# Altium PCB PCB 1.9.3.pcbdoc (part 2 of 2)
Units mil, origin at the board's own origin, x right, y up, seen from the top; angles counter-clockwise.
Board outline 4192.9 x 2374.1 mil, 2 copper layers (Top Layer, Bottom Layer), stack 62.2 mil thick; 67 components, 68 nets, 279 pads, 489 vias.
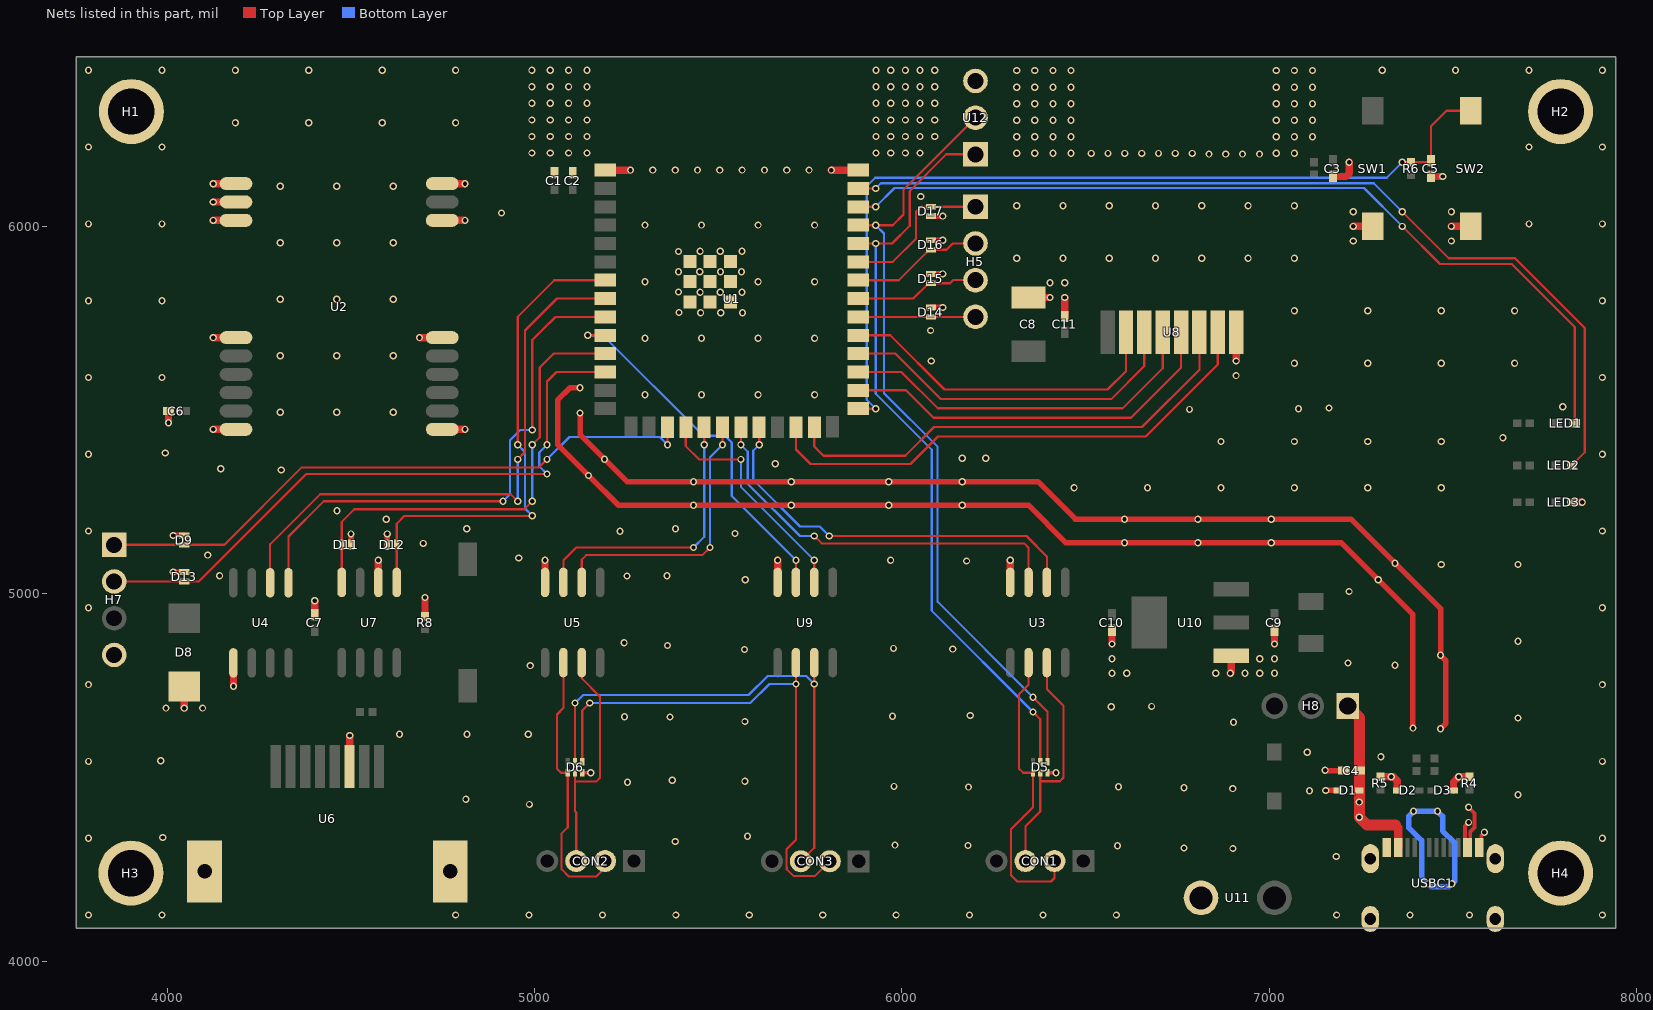
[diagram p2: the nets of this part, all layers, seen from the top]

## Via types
v1: diameter 19.7, hole 11.8, Top Layer to Bottom Layer, 489 vias

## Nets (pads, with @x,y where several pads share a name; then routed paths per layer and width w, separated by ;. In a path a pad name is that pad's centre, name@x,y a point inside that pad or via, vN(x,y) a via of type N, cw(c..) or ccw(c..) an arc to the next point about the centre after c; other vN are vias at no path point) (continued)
GND: C1.1 C2.1 C3.1 C4.1 C5.1 C6.1 C7.1 C8.2 C9.2 C10.1 C11.2 D1.1 D2.1 D3.1 D5.3 D6.3 D8.2 D9.1 D11.2 D12.2 D13.1 D14.1 D15.1 D16.1 D17.1 H1.1 H2.1 H3.1 H4.1 H7.4 LED3.1 R4.1 R5.1 R8.1 SW1.1 SW2.1 U1.1 U1.40 U1.41 U2.1 U2.2 U2.3 U2.4 U2.9 U2.10 U2.15 U2.16 U2.18 U3.4 U4.5 U5.4 U6.6 U6.9 U6.10 U7.2 U8.8 U9.4 U10.1 U11.1 U12.3 USBC1.0 USBC1.1 USBC1.2 USBC1.3 USBC1.A1 USBC1.A12 USBC1.B1 USBC1.B12 | length 8944.7
  Top Layer w6: v1(7152.7,4519.7) v1@7153.8,4518.7
  Top Layer w10: D6.3@5129.1,4512.9 v1(5152.1,4512.9) ; D5.3@6396.4,4512.9 v1(6419.4,4512.9) ; USBC1.A12@7578.1,4309.2 7578.1,4342.1 v1(7586.7,4350.7)
  Top Layer w15: v1(4015.1,5059.4) D13.1@4044.9,5059.4 ; v1(4015.1,5159.4) D9.1@4044.9,5159.4 ; D11.2@4499.3,5133.8 v1(4499.3,5163.6) ; D12.2@4598.1,5133.8 v1(4598.1,5163.6) ; v1(5123.1,5492.7) 5123.1,5433.7 v1(5189.7,5367.1) 5251.1,5305.7 v1(5432.1,5305.7) v1(5698.1,5305.7) v1(5964.1,5305.7) v1(6164.1,5305.7) 6370.6,5305.7 6472.6,5203.7 v1(6606.1,5203.7) v1(6806.1,5203.7) v1(7006.1,5203.7) 7223.1,5203.7 v1(7343.1,5083.7) 7467.1,4959.7 v1(7467.1,4832.7) 7481.9,4818 7481.9,4647.5 v1(7467.1,4632.7) ; v1(5123.1,5561.7) 5096.1,5561.7 5062.1,5527.7 5062.1,5406.7 v1(5146,5322.8) 5227.1,5241.7 v1(5432.1,5241.7) v1(5698.1,5241.7) v1(5964.1,5241.7) v1(6164.1,5241.7) 6344.1,5241.7 6446.1,5139.7 v1(6606.1,5139.7) v1(6806.1,5139.7) v1(7006.1,5139.7) 7196.6,5139.7 v1(7297.8,5038.5) 7392.1,4944.2 v1@7392.1,4632.7 ; D14.1@6079.1,5780.4 v1(6111.1,5780.4) ; D15.1@6079.1,5871.9 v1(6111.1,5871.9) ; D16.1@6079.1,5963.4 v1(6111.1,5963.4) ; D17.1@6079.1,6029.2 v1(6111.1,6029.2) ; v1@7153.8,4518.7 C4.1@7203,4518.7 ; v1(7154.7,4464.7) D1.1@7186.9,4464.7
  Top Layer w20: v1(4001.9,5466.3) C6.1@4001.9,5498.3 ; v1(4044.9,4689) D8.2@4044.9,4747.9 ; v1(4123.7,5448.3) U2.9@4185.9,5448.3 ; v1(4123.7,5698.3) U2.4@4185.9,5698.3 ; v1(4123.7,6017.6) U2.3@4185.9,6017.6 ; v1(4123.7,6067.6) U2.2@4185.9,6067.6 ; v1(4123.7,6117.6) U2.1@4185.9,6117.6 ; v1(4178.8,4748.7) U4.5@4178.8,4812.1 ; C7.1@4400.1,4943.6 v1(4400.1,4981.7) ; U6.6@4495.7,4529.7 v1(4495.7,4614.2) ; U7.2@4573.7,5031.3 v1(4573.7,5091.7) ; v1(4685.5,5698.3) U2.15@4747.7,5698.3 ; R8.1@4700.8,4939.2 v1(4700.8,4990.1) ; U2.10@4747.7,5448.3 v1(4809.8,5448.3) ; U2.16@4747.7,6017.6 v1(4809.8,6017.6) ; U2.18@4747.7,6117.6 v1(4809.8,6117.6) ; U5.4@5027.6,5031.3 v1(5027.6,5091.7) ; U1.1@5191.7,6154.6 v1(5260.6,6154.6) ; U9.4@5661.2,5031.3 v1(5661.2,5091.7) ; v1(5807.8,6154.6) U1.40@5880.7,6154.6 ; U3.4@6294.8,5031.3 v1(6294.8,5091.7) ; C8.2@6344.7,5807.5 v1(6403.3,5807.5) ; C11.2@6443.3,5755.7 v1(6443.3,5807.5) ; v1(6572.1,4863.7) C10.1@6572.1,4900.7 ; v1(6894.7,4783.7) 6897.2,4786.2 U10.1@6897.2,4831.6 ; v1(6910.3,5634.7) U8.8@6910.3,5712.8 ; v1(7014.7,4863.7) C9.2@7014.7,4900.7 ; C3.1@7174.1,6137.3 7209.7,6137.3 7218.1,6145.7 v1(7218.1,6175.8) ; v1(7229.7,6001.3) SW1.1@7282.1,6001.3 ; R5.1@7303.2,4501.8 7338.7,4501.8 7349.6,4490.8 D2.1@7349.6,4464.7 ; C5.1@7441.1,6137.3 v1(7473.1,6137.3) ; v1(7496.7,6001.3) SW2.1@7549.1,6001.3 ; D3.1@7502.7,4464.7 7502.7,4487.8 v1(7516.7,4501.8) R4.1@7546.2,4501.8 ; LED3.1@7824.4,5249.9 v1(7852.9,5249.9)
  Bottom Layer w15: 7380.7,4362.7 7380.7,4394.7 v1(7393.7,4407.7) v1(7458.7,4407.7) 7472.7,4393.7 7472.7,4354.7 7506,4321.5 7506,4218.6 v1(7498.1,4210.7) 7489.1,4201.8 7442.1,4201.8 v1(7433.1,4210.7) 7415.7,4228.1 7415.7,4327.7 7380.7,4362.7
  other v1: 3784.1,4125.5 3984.1,4125.5 4784.1,4125.5 4984.1,4125.5 5184.1,4125.5 5384.1,4125.5 5584.1,4125.5 5784.1,4125.5 5984.1,4125.5 6184.1,4125.5 6384.1,4125.5 6584.1,4125.5 7184.1,4125.5 7384.1,4125.5 7546.1,4125.5 7908.1,4125.5 7183.1,4284.7 6901.5,4306.7 6768.1,4307.7 6587.1,4313.7 6180.1,4314.7 5981.1,4315.7 5382.1,4325.7 3784.1,4334.7 7908.1,4334.7 3986.1,4336.7 5579.1,4339.7 4985.1,4426.7 4812.1,4440.7 7678.1,4452.7 7110.1,4463.7 6901.1,4469.7 6768.1,4471.7 6181.1,4473.7 6590.1,4474.7 5978.1,4475.7 5252.1,4486.7 5572.1,4489.7 5374.1,4492.7 7332.7,4501.8 3784.1,4543.8 7908.1,4543.8 3981.1,4545.7 7304.7,4556.7 7104.1,4568.7 4631.1,4617.7 4815.1,4617.7 4982.1,4617.7 7392.1,4634.5 6903.1,4650.7 5572.1,4652.7 7678.1,4661.9 5368.1,4664.7 5244.1,4665.7 5974.1,4666.7 6186.1,4668.7 3994.9,4689 4094.9,4689 6570.1,4692.7 6680.1,4693.7 3784.1,4753 7908.1,4753 6572.1,4783.7 6612.1,4783.7 6854.7,4783.7 6934.7,4783.7 6974.7,4783.7 7014.7,4783.7 4987.1,4804.7 7343.1,4805.7 7215.1,4811.7 6572.1,4823.7 6974.7,4823.7 7014.7,4823.7 5571.1,4848.7 6138.1,4849.7 5977.1,4851.7 5361.1,4859.7 5243.1,4866.7 7678.1,4871.1 3784.1,4962.2 7908.1,4962.2 7218.1,5006.7 5573.1,5038.7 5251.1,5048.7 4141.1,5049.7 5360.1,5049.7 7469,5080.3 7678.1,5080.3 6176.1,5089.7 5969.1,5091.7 4956.1,5097.7 4109.1,5105.7 4696.1,5137.7 5545.1,5164.7 3784.1,5171.4 5232.1,5170.7 7908.1,5171.4 4814.1,5177.7 5383.1,5177.7 4595.1,5203.7 4461.1,5226.7 6469,5289.4 6669,5289.4 6869,5289.4 7069,5289.4 7269,5289.4 7469,5289.4 4309.1,5337.7 4144.1,5340.7 5655.1,5354.7 6164.1,5369.7 6228.1,5369.7 3784.1,5380.6 7908.1,5380.6 3993.1,5383.7 6869,5415.4 7069,5415.4 7269,5415.4 7469,5415.4 7637.1,5425.7 4306.1,5494.7 4460.1,5494.7 4614.1,5494.7 6783.1,5502.7 7080.1,5504.7 7163.1,5506.7 7800.1,5509.7 5300.1,5542.7 5454.1,5542.7 5608.1,5542.7 5762.1,5542.7 3784.1,5589.7 3984.1,5589.7 7908.1,5589.7 6910.3,5594.7 7069,5628.4 7269,5628.4 7469,5628.4 7669,5628.4 6080.1,5634.7 4306.1,5648.7 4460.1,5648.7 4614.1,5648.7 5300.1,5696.7 5454.1,5696.7 5608.1,5696.7 5762.1,5696.7 6078.1,5717.7 5451.5,5765.7 5506.5,5765.7 5565.5,5765.7 5392.5,5766.7 7069,5771.4 7269,5771.4 7469,5771.4 7669,5771.4 3784.1,5798.9 3984.1,5798.9 7908.1,5798.9 4306.1,5802.7 4460.1,5802.7 4614.1,5802.7 5450.1,5821.7 5505.1,5821.7 5564.1,5821.7 5391.1,5822.7 6403.3,5847.5 6443.3,5847.5 5300.1,5850.7 5608.1,5850.7 5762.1,5850.7 5391.1,5877.7 5449.1,5877.7 5505.8,5877.7 5562.7,5877.7 6312.6,5914.4 6438.6,5914.4 6564.7,5914.4 6690.8,5914.4 6816.8,5914.4 6942.9,5914.4 7069,5914.4 5391.1,5932.7 5450.1,5933.7 5505.1,5933.7 5564.1,5933.7 4306.1,5956.7 4460.1,5956.7 4614.1,5956.7 7229.7,5961.3 7496.7,5961.3 5300.1,6004.7 5454.1,6004.7 5608.1,6004.7 5762.1,6004.7 3784.1,6008.1 3984.1,6008.1 7708.1,6008.1 7908.1,6008.1 4909.1,6037.7 7229.7,6041.3 7496.7,6041.3 6312.6,6057.4 6438.6,6057.4 6564.7,6057.4 6690.8,6057.4 6816.8,6057.4 6942.9,6057.4 7069,6057.4 6051.1,6082.7 4306.1,6110.7 4460.1,6110.7 4614.1,6110.7 5321.4,6154.6 5382.2,6154.6 5443,6154.6 5503.8,6154.6 5564.6,6154.6 5625.4,6154.6 5686.2,6154.6 5747,6154.6 6836.3,6198.1 6882.1,6198.1 6927.9,6198.1 6973.8,6198.1 6312.6,6200.4 6361.9,6200.4 6411.3,6200.4 6460.6,6200.4 6515.5,6200.1 6561.3,6200.1 6607.1,6200.1 6653,6200.1 6698.8,6200.1 6744.6,6200.1 6790.5,6200.1 7019.6,6200.4 7069,6200.4 4991.9,6201.3 5041.9,6201.3 5091.9,6201.3 5141.9,6201.3 5929.3,6201.3 5969.3,6201.3 6009.3,6201.3 6049.3,6201.3 3784.1,6217.3 3984.1,6217.3 7708.1,6217.3 7908.1,6217.3 4991.9,6246.3 5041.9,6246.3 5091.9,6246.3 5141.9,6246.3 5929.3,6246.3 5969.3,6246.3 6009.3,6246.3 6049.3,6246.3 6089.3,6246.3 6312.6,6245.5 6361.9,6245.5 6411.3,6245.5 6460.6,6245.5 7019.6,6245.5 7069,6245.5 7118.3,6245.5 4184.1,6283.5 4384.1,6283.5 4584.1,6283.5 4784.1,6283.5 6312.6,6290.5 6361.9,6290.5 6411.3,6290.5 6460.6,6290.5 7019.6,6290.5 7069,6290.5 7118.3,6290.5 4991.9,6291.3 5041.9,6291.3 5091.9,6291.3 5141.9,6291.3 5929.3,6291.3 5969.3,6291.3 6009.3,6291.3 6049.3,6291.3 6089.3,6291.3 4991.9,6336.4 5041.9,6336.4 5091.9,6336.4 5141.9,6336.4 5929.3,6336.4 5969.3,6336.4 6009.3,6336.4 6049.3,6336.4 6089.3,6336.4 6312.6,6335.6 6361.9,6335.6 6411.3,6335.6 6460.6,6335.6 7019.6,6335.6 7069,6335.6 7118.3,6335.6 4991.9,6381.4 5041.9,6381.4 5091.9,6381.4 5141.9,6381.4 5929.3,6381.4 5969.3,6381.4 6009.3,6381.4 6049.3,6381.4 6089.3,6381.4 6312.6,6380.6 6361.9,6380.6 6411.3,6380.6 6460.6,6380.6 7019.6,6380.6 7069,6380.6 7118.3,6380.6 3784.1,6426.5 3984.1,6426.5 4184.1,6426.5 4384.1,6426.5 4584.1,6426.5 4784.1,6426.5 4991.9,6426.5 5041.9,6426.5 5091.9,6426.5 5141.9,6426.5 5929.3,6426.5 5969.3,6426.5 6009.3,6426.5 6049.3,6426.5 6089.3,6426.5 6312.6,6425.7 6361.9,6425.7 6411.3,6425.7 6460.6,6425.7 7019.6,6425.7 7069,6425.7 7118.3,6425.7 7308.1,6426.5 7508.1,6426.5 7708.1,6426.5 7908.1,6426.5
IO0: C5.2 R6.1 SW2.2 U1.27 | length 2448.8
  Top Layer w6: U1.27@5880.7,5504.6 v1(5928.4,5504.6) ; v1(7363.1,6175.8) R6.1@7387.1,6175.8 7436.7,6175.8 C5.2@7441.1,6180.3 7441.1,6273.7 7483.6,6316.3 SW2.2@7549.1,6316.3
  Bottom Layer w6: v1(5928.4,5504.6) 5904.1,5529 5904.1,6110.7 5927.1,6133.7 7321,6133.7 v1(7363.1,6175.8)
IO39: D14.2 H5.4 U1.32 | length 319.7
  Top Layer w6: U1.32@5880.7,5754.6 6200.1,5754.6 H5.4@6200.3,5754.8
IO40: D15.2 H5.3 U1.33 | length 340.4
  Top Layer w6: U1.33@5880.7,5804.6 6031,5804.6 6072.6,5846.3 D15.2@6079.1,5846.3 6130.6,5846.3 6139.2,5854.8 H5.3@6200.3,5854.8
IO41: D16.2 H5.2 U1.34 | length 361.1
  Top Layer w6: U1.34@5880.7,5854.6 5991,5854.6 6074.1,5937.8 D16.2@6079.1,5937.8 6121.5,5937.8 6138.6,5954.8 H5.2@6200.3,5954.8
IO42: D17.2 H5.1 U1.35 | length 424.6
  Top Layer w6: U1.35@5880.7,5904.6 5975,5904.6 6038.1,5967.7 6038.1,6040.7 6052.2,6054.8 D17.2@6079.1,6054.8 H5.1@6200.3,6054.8
LED1_INVERTER: LED2.1 U1.39 | length 2538
  Top Layer w6: U1.39@5880.7,6104.6 v1(5928.4,6104.6) ; v1(7363.1,6041.3) 7489.6,5914.7 7670.1,5914.7 7860.1,5724.7 7860.1,5385.6 LED2.1@7824.4,5349.9
  Bottom Layer w6: v1(5928.4,6104.6) 5942.5,6118.7 7285.6,6118.7 v1(7363.1,6041.3)
LED1_NETWORK: LED1.2 U1.38 | length 2392.2
  Top Layer w6: U1.38@5880.7,6054.6 v1(5928.4,6054.6) ; v1(7363.1,6001.3) 7465.6,5898.7 7661.1,5898.7 7832.7,5727.1 LED1.2@7832.7,5464.9
  Bottom Layer w6: v1(5928.4,6054.6) 5979.5,6105.7 7258.6,6105.7 v1(7363.1,6001.3)
MPPT1_RX: U1.20 U5.2 | length 767.1
  Top Layer w6: U5.2@5127.6,5031.3 5127.6,5093.2 5140.1,5105.7 5456.2,5105.7 v1(5477.2,5126.7) ; v1(5511.2,5406.5) U1.20@5511.2,5454.3
  Bottom Layer w6: v1(5477.2,5126.7) 5477.2,5372.5 v1(5511.2,5406.5)
MPPT1_TX: U1.19 U5.3 | length 768.7
  Top Layer w6: U5.3@5077.6,5031.3 5077.6,5091.2 5113.1,5126.7 v1(5432.1,5126.7) ; v1(5461.2,5406.5) U1.19@5461.2,5454.3
  Bottom Layer w6: v1(5432.1,5126.7) 5461.2,5155.9 v1(5461.2,5406.5)
MPPT2_RX: U1.18 U9.2 | length 634.7
  Top Layer w6: U1.18@5411.2,5454.3 5411.2,5402.6 5447.3,5366.5 v1(5561.2,5366.5) ; U9.2@5761.2,5031.3 v1(5761.2,5091.7)
  Bottom Layer w6: v1(5561.2,5366.5) 5561.2,5291.7 v1(5761.2,5091.7)
MPPT2_TX: U1.10 U9.3 | length 1014.6
  Top Layer w6: v1(5144,5704.6) U1.10@5191.7,5704.6 ; U9.3@5711.2,5031.3 v1(5711.2,5091.7)
  Bottom Layer w6: v1(5144,5704.6) 5185.2,5704.6 5459.1,5430.7 5518.1,5430.7 5536.1,5412.7 5536.1,5266.8 v1(5711.2,5091.7)
NRF_CE: U1.31 U8.2 | length 917.6
  Top Layer w6: U1.31@5880.7,5704.6 5968.2,5704.6 6116.1,5556.7 6560.1,5556.7 6610.3,5606.9 U8.2@6610.3,5712.8
NRF_CS: U1.30 U8.3 | length 960.2
  Top Layer w6: U1.30@5880.7,5654.6 5982.2,5654.6 6106.1,5530.7 6570.1,5530.7 6660.3,5620.9 U8.3@6660.3,5712.8
NRF_IRQ: U1.24 U8.7 | length 1426.6
  Top Layer w6: U1.24@5711.2,5454.3 5711.2,5393.6 5751.1,5353.7 6023.1,5353.7 6098.1,5428.7 6664.1,5428.7 6860.3,5624.9 U8.7@6860.3,5712.8
NRF_MISO: U1.25 U8.6 | length 1311
  Top Layer w6: U1.25@5761.2,5454.3 5761.2,5401.6 5786.1,5376.7 6009.1,5376.7 6087.1,5454.7 6654.1,5454.7 6810.3,5610.9 U8.6@6810.3,5712.8
NRF_MOSI: U1.28 U8.5 | length 1063.9
  Top Layer w6: U1.28@5880.7,5554.6 6011.2,5554.6 6086.1,5479.7 6624.1,5479.7 6760.3,5615.9 U8.5@6760.3,5712.8
NRF_SCK: U1.29 U8.4 | length 1013.7
  Top Layer w6: U1.29@5880.7,5604.6 5998.2,5604.6 6097.1,5505.7 6601.1,5505.7 6710.3,5614.9 U8.4@6710.3,5712.8
OLED_SCL: D13.2 H7.2 U1.12 | length 1739.4
  Top Layer w6: H7.2@3853.9,5033.8 D13.2@4044.9,5033.8 4084.2,5033.8 4376.9,5326.5 v1(5033.1,5326.5) ; v1(5033.1,5406.5) 5033.1,5578.7 5059,5604.6 U1.12@5191.7,5604.6
  Bottom Layer w6: v1(5033.1,5326.5) 5012.1,5347.5 5012.1,5385.5 v1(5033.1,5406.5)
OLED_SDA: D9.2 H7.1 U1.17 | length 1685.6
  Top Layer w6: H7.1@3853.9,5133.8 D9.2@4044.9,5133.8 4154.2,5133.8 4365.1,5344.7 5011.3,5344.7 v1(5033.1,5366.5) ; v1(5361.2,5406.5) U1.17@5361.2,5454.3
  Bottom Layer w6: v1(5033.1,5366.5) 5094.3,5427.7 5340,5427.7 v1(5361.2,5406.5)
PY_CAN_RX: D11.1 U1.11 U7.4 | length 1274.3
  Top Layer w6: U7.4@4473.7,5031.3 D11.1@4473.7,5133.8 4473.7,5196.3 4508.1,5230.7 4971.1,5230.7 v1(4993.1,5252.7) ; v1(4993.1,5406.5) 5013.1,5426.5 5013.1,5616.7 5051,5654.6 U1.11@5191.7,5654.6
  Bottom Layer w6: v1(4993.1,5252.7) v1(4993.1,5406.5)
PY_CAN_TX: D12.1 U1.7 U7.1 | length 1376.8
  Top Layer w6: U7.1@4623.7,5031.3 D12.1@4623.7,5133.8 4623.7,5191.3 4645.1,5212.7 v1(4993.1,5212.7) ; v1(4953.1,5406.5) 4953.1,5754.7 5053,5854.6 U1.7@5191.7,5854.6
  Bottom Layer w6: v1(4953.1,5406.5) 4973.1,5386.5 4973.1,5232.7 v1(4993.1,5212.7)
RE#: U1.8 U4.2 | length 1571.5
  Top Layer w6: U4.2@4278.8,5030.4 4278.8,5135.4 4415.1,5271.7 4934.1,5271.7 v1(4953.1,5252.7) ; v1(4953.1,5366.5) 4973.1,5386.5 4973.1,5717.7 5060,5804.6 U1.8@5191.7,5804.6
  Bottom Layer w6: v1(4953.1,5252.7) v1(4953.1,5366.5)
RO: U1.9 U4.1 | length 1466.4
  Top Layer w6: U4.1@4328.8,5030.4 4328.8,5156.4 4425.1,5252.7 v1(4913.1,5252.7) ; v1(4993.1,5446.5) 4993.1,5691.7 5019.6,5718.2 5056,5754.6 U1.9@5191.7,5754.6
  Bottom Layer w6: v1(4913.1,5252.7) 4932.1,5271.7 4932.1,5418.7 4959.9,5446.5 v1(4993.1,5446.5)
RX1: CON1.3 D5.2 U3.7 | length 656.9
  Top Layer w6: CON1.3@6336.6,4272.2 6336.6,4367.3 6376.7,4407.4 6376.7,4489.7 ; D5.2@6376.7,4512.9 6376.7,4489.7 ; U3.7@6394.8,4813 6394.8,4741 6440.1,4695.7 6440.1,4499.7 6430.1,4489.7 6376.7,4489.7
RX2: CON2.3 D6.2 U5.7 | length 648.6
  Top Layer w6: D6.2@5109.4,4512.9 5109.4,4488.7 ; CON2.3@5112.6,4272.2 5112.6,4404.9 5109.4,4408.1 5109.4,4488.7 ; U5.7@5127.6,4813 5127.6,4770.3 5177.1,4720.7 5177.1,4498.7 5167.1,4488.7 5109.4,4488.7
RX3: CON3.3 D6.5 U9.7 | length 1407.5
  Top Layer w6: D6.5@5109.4,4543.2 v1(5109.4,4702.7) ; CON3.3@5724.6,4271.7 5761.2,4308.3 U9.7@5761.2,4813
  Bottom Layer w6: v1(5109.4,4702.7) 5131.4,4724.7 5582.1,4724.7 5634.1,4776.7 5739,4776.7 v1(5761.2,4754.6)
RXD0: D5.5 U1.36 U12.1 | length 2072.9
  Top Layer w6: U1.36@5880.7,5954.6 v1(5928.4,5954.6) 5973,5954.6 6021.1,6002.7 6021.1,6097.7 6120.9,6197.5 U12.1@6200.3,6197.5 ; v1(6357,4678.5) 6376.7,4658.8 D5.5@6376.7,4543.2
  Bottom Layer w6: v1(5928.4,5954.6) 5928.4,5545.4 6081.1,5392.7 6081.1,4954.5 v1(6357,4678.5)
SHUNT_RX: U1.22 U3.2 | length 1107.1
  Top Layer w6: v1(5611.2,5406.5) U1.22@5611.2,5454.3 ; v1(5802.1,5157.7) 6339.1,5157.7 6394.8,5102 U3.2@6394.8,5031.3
  Bottom Layer w6: v1(5611.2,5406.5) 5595.1,5390.4 5595.1,5310.7 5722.1,5183.7 5776.1,5183.7 v1(5802.1,5157.7)
SHUNT_TX: U1.21 U3.3 | length 1093.8
  Top Layer w6: v1(5561.2,5406.5) U1.21@5561.2,5454.3 ; v1(5761.2,5157.7) 5781.2,5137.7 6333.1,5137.7 6344.8,5126 U3.3@6344.8,5031.3
  Bottom Layer w6: v1(5561.2,5406.5) 5580.1,5387.6 5580.1,5299.7 5722.1,5157.7 v1(5761.2,5157.7)
TX1: CON1.2 D5.1 U3.6 | length 821.6
  Top Layer w6: U3.6@6344.8,4813 6344.8,4752.5 6319.1,4726.7 6319.1,4523.7 6330,4512.9 D5.1@6357,4512.9 6357,4418.7 6297.1,4358.7 6297.1,4233.7 6314.1,4216.7 6406.1,4216.7 6415.3,4226 CON1.2@6415.3,4272.2
TX2: CON2.2 D6.1 U5.6 | length 755
  Top Layer w6: 5072.8,4288.3 5072.8,4249.9 5092.4,4230.4 5167.3,4230.4 5191.3,4254.4 CON2.2@5191.3,4272.2 ; 5072.8,4288.4 5072.8,4347.7 5089.8,4364.6 D6.1@5089.8,4512.9 5071,4512.9 5060.1,4523.7 5060.1,4671.7 5077.6,4689.2 U5.6@5077.6,4813
TX3: CON3.2 D6.4 U9.6 | length 1466.2
  Top Layer w6: D6.4@5129.1,4543.2 5129.1,4682.4 v1(5149.4,4702.7) ; U9.6@5711.2,4813 v1(5711.2,4754.6) 5711.2,4330.4 5685.6,4304.8 5685.6,4255.6 5686,4255.2 5686,4250.1 5704.2,4231.9 5763.5,4231.9 CON3.2@5803.3,4271.7
  Bottom Layer w6: v1(5149.4,4702.7) 5587.1,4702.7 5638.9,4754.6 v1(5711.2,4754.6)
TXD0: D5.4 U1.37 U12.2 | length 2135.8
  Top Layer w6: U1.37@5880.7,6004.6 v1(5928.4,6004.6) 5975,6004.6 6004.1,6033.7 6004.1,6101.3 U12.2@6200.3,6297.5 ; v1(6357,4718.5) 6396.4,4679.1 D5.4@6396.4,4543.2
  Bottom Layer w6: v1(5928.4,6004.6) 5951.1,5982 5951.1,5546.7 6097.1,5400.7 6097.1,4978.5 v1(6357,4718.5)
VBUS: C4.2 D1.2 H8.1 USBC1.A4 USBC1.A9 USBC1.B4 USBC1.B9 | length 745.7
  Top Layer w10: USBC1.B4@7533.8,4310.2 7533.8,4367.8 v1(7543.6,4377.7) ; v1(7543.6,4418.7) 7559.7,4402.6 7559.7,4363.7 7547.7,4351.6 USBC1.A9@7547.7,4310.4
  Top Layer w11.8: 7296.5,4370.7 7298.9,4373.1 ; USBC1.A4@7345.8,4309.2 7345.8,4369.4 ; 7349.5,4373.1 7357.6,4365 USBC1.B9@7357.6,4309.2
  Top Layer w30: H8.1@7214.7,4694.9 7246,4663.6 C4.2@7246,4518.7 D1.2@7246,4464.7 v1(7246,4432.9) 7246,4391.5 7266.7,4370.7 7296.5,4370.7 7344.4,4370.7
  other v1: 7246,4391.9
pads on no net: U1.15 U2.5 U2.6 U2.7 U2.17 U6.3 U6.7 U6.8 U7.5 USBC1.A8 USBC1.B8

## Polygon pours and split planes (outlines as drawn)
$1N172 on Top Layer (solid, remove dead copper, pour order 0): 6962.1,4133.7 6980.1,4115.7 7052.1,4115.7 7072,4135.7 7072,4446.8 7054.1,4464.7 6978.1,4464.7 6962.1,4448.7
EXT_5V on Top Layer (solid, remove dead copper, pour order 2): 6964.7,4715.9 6964.7,4556.5 6978.2,4542.9 7046.3,4542.9 7058.1,4554.7 7058.1,4718.7 7042.9,4733.9 6982.7,4733.9
$1N148 on Top Layer (solid, remove dead copper, pour order 4): 7159.7,4668.9 7159.7,4881.3 7150.2,4890.9 7080.1,4890.9 7071.3,4882.1 7071.3,4671.1 7089.5,4652.9 7143.7,4652.9
+5V on Top Layer (solid, remove dead copper, pour order 6): 6845.1,4981.7 6853.1,4973.7 6964.1,4973.7 6983.1,4954.7 6983.1,4938.3 6996.3,4925.1 7148.5,4925.1 7155.1,4931.7 7155.1,5052.7 7144.1,5063.7 6856.1,5063.7 6845.1,5052.7
+3V3 on Top Layer (solid, remove dead copper, pour order 8): 6429.1,5067.7 6429.1,4940.9 6442.8,4927.1 6604.7,4927.1 6615.1,4916.7 6615.1,4850.7 6626.1,4839.7 6720.1,4839.7 6757.1,4876.7 6939.1,4876.7 6949.1,4886.7 6949.1,4944.7 6939.1,4954.7 6792.1,4954.7 6670.1,5076.7 6438.1,5076.7
VBUS on Top Layer (solid, remove dead copper, pour order 10): 7528.1,4283.7 7530.1,4281.7 7550.1,4281.7 7552.1,4283.7 7552.1,4348.8 7564.6,4361.3 7564.6,4425.3 7560.8,4429 7536.8,4429 7528.1,4420.3
VBUS on Top Layer (solid, remove dead copper, pour order 12): 7317.7,4361.6 7339.1,4340.1 7339.1,4283.7 7340.1,4282.7 7362.1,4282.7 7363.1,4283.7 7363.1,4365.6 7343,4385.7 7321.2,4385.7 7317.7,4382.2
VBUS on Bottom Layer (solid, remove dead copper, pour order 18): 7227.1,4446.7 7227.1,4386.7 7235.1,4378.7 7260.1,4378.7 7313.1,4431.7 7494.1,4431.7 7511.1,4414.7 7511.1,4369.7 7516.1,4364.7 7552.1,4364.7 7558.1,4370.7 7558.1,4436.7 7521.1,4473.7 7254.1,4473.7
+3V3 on Top Layer (solid, remove dead copper, pour order 14): 6296.1,5692.7 6296.1,5613.7 6306.1,5603.7 6381.1,5603.7 6397.1,5619.7 6397.1,5694.8 6390.7,5701.2 6304.6,5701.2
+3V3 on Bottom Layer (solid, remove dead copper, pour order 20): 6314.1,5619.7 6314.1,5373.7 6433.1,5254.7 6433.1,4947.7 6438.1,4942.7 6488.1,4942.7 6495.1,4949.7 6495.1,5295.7 6375.1,5415.7 6375.1,5619.7 6368.1,5626.7 6321.1,5626.7
+5V on Bottom Layer (solid, remove dead copper, pour order 22): 6952.1,5037.7 7022.1,5037.7 7028.1,5031.7 7028.1,4972.7 7016.1,4960.7 6920.1,4960.7 6905.4,4975.4 6905.4,4991.1
+3V3 on Bottom Layer (solid, remove dead copper, pour order 24): 4552.1,4966.7 4537.1,4981.7 4517.1,4981.7 4510.1,4974.7 4510.1,4927.7 4525.1,4912.7 5028.2,4912.7 5036.2,4920.7 5036.2,4956.7 5026.1,4966.7
GND on Top Layer (solid, remove dead copper, pour order 16): 3750.1,6457.9 3750.1,4083.8 7943.1,4083.8 7943.1,6455.8 7942.1,6455.8 7942.1,6457.9
GND on Bottom Layer (solid, remove dead copper, pour order 26): 3751.1,6463.8 3751.1,4089.7 7944.1,4089.7 7944.1,6461.7 7943.1,6461.7 7943.1,6463.8

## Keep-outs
Top Layer:
  region: 5121.1,4526.7 5121.1,4496.7 5168.5,4496.7 5168.5,4526.7
  region: 6386.1,4525.7 6386.1,4496.7 6432.1,4496.7 6432.1,4525.7
  region: 5056.1,5002.7 5056.1,4952.7 5065.1,4952.7 5065.1,5002.7
  region: 5199.1,5096.7 5191.1,5096.7 5191.1,5058.7 5199.1,5058.7
  region: 5690.1,5001.7 5690.1,4951.7 5699.1,4951.7 5699.1,5001.7
  region: 5714.1,5110.7 5714.1,5102.7 5763.1,5102.7 5763.1,5110.7
  region: 6324.1,5002.7 6324.1,4952.7 6332.1,4952.7 6332.1,5002.7
  region: 4207.1,4841.7 4207.1,4921.2 4216.3,4921.2 4216.3,4841.7
  region: 4800.1,5707.7 4800.1,5657.7 4809.1,5657.7 4809.1,5707.7
  region: 6062.3,6042 6062.3,5619.7 6038.1,5619.7 6038.1,6042
  region: 6243.1,6232.7 6243.1,6297.5 6232.7,6297.5 6232.7,6232.7
  region: 6995.6,4915.6 6956.2,4915.6 6956.2,4923.2 6995.6,4923.2
Board Outline Layer:
  region: 5172.3,6466.8 5172.3,6203.7 5899.1,6203.7 5899.1,6466.8
  region: 5172.3,6466.8 5172.3,6203.7 5899.1,6203.7 5899.1,6466.8
  region: 6491.1,6469.7 6491.1,6240.7 6981.1,6240.7 6981.1,6469.7
  region: 6491.1,6469.7 6491.1,6240.7 6981.1,6240.7 6981.1,6469.7
  lines w0.1: 5172.3,6203.7 5172.3,6466.8 5899.1,6466.8 5899.1,6203.7 5172.3,6203.7 ; 6491.1,6240.7 6491.1,6469.7 6981.1,6469.7 6981.1,6240.7 6491.1,6240.7
  lines w10: 3751.1,4089.7 3751.1,6463.8 7944,6463.8 7944,4089.7 3751.1,4089.7

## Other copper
Top Layer:
  drawing of 378 lines, arcs and shapes, not listed
Bottom Layer:
  region net TX3: 5697.8,4751.6 5697.8,4757.6 5698.9,4757.7 5699.9,4757.9 5700.7,4758.4 5701.5,4758.9 5703,4760.3 5704.6,4761.9 5704.6,4747.2 5703,4748.8 5701.5,4750.2 5700.7,4750.8 5699.9,4751.2 5698.9,4751.5
  region net RX3: 5749.6,4762 5753.8,4766.2 5754.7,4765.5 5755.6,4765 5756.5,4764.7 5757.4,4764.5 5759.5,4764.4 5761.8,4764.4 5751.4,4754 5751.3,4756.3 5751.3,4758.4 5751.1,4759.3 5750.8,4760.2 5750.3,4761.1
  region net MPPT2_TX: 5699.6,5099.1 5703.8,5103.4 5704.7,5102.7 5705.6,5102.2 5706.5,5101.8 5707.4,5101.7 5709.5,5101.6 5711.8,5101.6 5701.4,5091.2 5701.3,5093.5 5701.3,5095.5 5701.1,5096.5 5700.8,5097.4 5700.3,5098.3
  region net MPPT2_RX: 5749.6,5099.1 5753.8,5103.4 5754.7,5102.7 5755.6,5102.2 5756.5,5101.8 5757.4,5101.7 5759.5,5101.6 5761.8,5101.6 5751.4,5091.2 5751.3,5093.5 5751.3,5095.5 5751.1,5096.5 5750.8,5097.4 5750.3,5098.3
  region net RXD0: 6345.4,4685.9 6349.6,4690.1 6350.5,4689.4 6351.4,4688.9 6352.3,4688.6 6353.3,4688.4 6355.3,4688.4 6357.6,4688.3 6347.2,4678 6347.2,4680.3 6347.1,4682.3 6346.9,4683.2 6346.6,4684.2 6346.1,4685
  region net TXD0: 6345.4,4725.9 6349.6,4730.1 6350.5,4729.4 6351.4,4728.9 6352.3,4728.6 6353.3,4728.4 6355.3,4728.4 6357.6,4728.3 6347.2,4718 6347.2,4720.3 6347.1,4722.3 6346.9,4723.2 6346.6,4724.2 6346.1,4725
  region net DN: 7422.4,4377.4 7416,4371.1 7414.8,4372 7413.3,4372.5 7411.8,4372.8 7410.2,4372.9 7420.6,4383.3 7420.7,4381.7 7421,4380.1 7421.5,4378.7
  region net DP: 7436.4,4371.1 7430,4377.4 7431,4378.7 7431.5,4380.1 7431.8,4381.7 7431.9,4383.3 7442.3,4372.9 7440.7,4372.8 7439.1,4372.5 7437.7,4372
  region net DN: 7455.4,4247.4 7461.8,4241.1 7460.9,4239.8 7460.3,4238.4 7460.1,4236.8 7459.9,4235.2 7449.6,4245.6 7451.2,4245.7 7452.7,4246 7454.2,4246.5
  region net DP: 7469.4,4241.1 7475.8,4247.4 7477,4246.5 7478.5,4246 7480,4245.7 7481.6,4245.6 7471.3,4235.2 7471.1,4236.8 7470.9,4238.4 7470.3,4239.8
  region net GND: 7419.4,4213.8 7430.1,4224.4 7431.7,4222.9 7433.3,4221.7 7436.4,4219.7 7438.8,4218.5 7440.1,4217.7 7426.1,4203.8 7425.4,4205.1 7424.1,4207.5 7422.2,4210.6 7420.9,4212.2
  region net CMT_FCS: 4890.2,5710 4894.5,5705.7 4893.8,5704.9 4893.3,5704 4892.9,5703.1 4892.8,5702.1 4892.7,5700.1 4892.7,5697.8 4882.3,5708.2 4884.6,5708.2 4886.6,5708.3 4887.6,5708.4 4888.5,5708.7 4889.4,5709.2
  region net EN: 5157.4,6057.6 5157.4,6051.7 5156.3,6051.6 5155.3,6051.3 5154.5,6050.9 5153.7,6050.3 5152.2,6048.9 5150.6,6047.3 5150.6,6062 5152.2,6060.4 5153.7,6059 5154.5,6058.4 5155.3,6058 5156.3,6057.7
  region net TXD0: 5940.1,5997.2 5935.8,5993 5935,5993.7 5934.1,5994.2 5933.2,5994.6 5932.2,5994.7 5930.2,5994.8 5927.9,5994.8 5938.3,6005.2 5938.3,6002.9 5938.4,6000.9 5938.5,5999.9 5938.8,5999 5939.3,5998.1
  region net RXD0: 5931.4,5941.2 5925.4,5941.2 5925.3,5942.3 5925.1,5943.3 5924.6,5944.2 5924.1,5944.9 5922.7,5946.4 5921.1,5948.1 5935.8,5948.1 5934.2,5946.4 5932.8,5944.9 5932.2,5944.2 5931.8,5943.3 5931.5,5942.3
  region net LED1_NETWORK: 5935.8,6066.3 5940.1,6062 5939.3,6061.2 5938.8,6060.3 5938.5,6059.4 5938.4,6058.4 5938.3,6056.4 5938.3,6054.1 5927.9,6064.5 5930.2,6064.5 5932.2,6064.6 5933.2,6064.7 5934.1,6065 5935,6065.5
  region net LED1_INVERTER: 5935.8,6116.3 5940.1,6112 5939.3,6111.2 5938.8,6110.3 5938.5,6109.4 5938.4,6108.4 5938.3,6106.4 5938.3,6104.1 5927.9,6114.5 5930.2,6114.5 5932.2,6114.6 5933.2,6114.7 5934.1,6115 5935,6115.5
  region net IO0: 5916.8,5512 5921,5516.3 5921.9,5515.5 5922.8,5515 5923.7,5514.7 5924.6,5514.6 5926.7,5514.5 5929,5514.5 5918.6,5504.1 5918.6,5506.4 5918.5,5508.4 5918.3,5509.4 5918,5510.3 5917.5,5511.2
  region net EN: 7090.7,6164.2 7086.5,6168.4 7087.2,6169.3 7087.7,6170.2 7088,6171.1 7088.2,6172.1 7088.2,6174.1 7088.3,6176.4 7098.6,6166 7096.4,6166 7094.3,6165.9 7093.4,6165.7 7092.5,6165.4 7091.6,6164.9
  region net IO0: 7355.7,6164.2 7351.4,6168.4 7352.2,6169.3 7352.7,6170.2 7353,6171.1 7353.1,6172.1 7353.2,6174.1 7353.2,6176.4 7363.6,6166 7361.3,6166 7359.3,6165.9 7358.3,6165.7 7357.4,6165.4 7356.6,6164.9
  region net LED1_INVERTER: 7351.4,6048.7 7355.7,6052.9 7356.6,6052.2 7357.4,6051.7 7358.3,6051.4 7359.3,6051.2 7361.3,6051.2 7363.6,6051.1 7353.2,6040.8 7353.2,6043.1 7353.1,6045.1 7353,6046 7352.7,6047 7352.2,6047.8
  region net LED1_NETWORK: 7351.4,6008.7 7355.7,6012.9 7356.6,6012.2 7357.4,6011.7 7358.3,6011.4 7359.3,6011.2 7361.3,6011.2 7363.6,6011.1 7353.2,6000.8 7353.2,6003.1 7353.1,6005.1 7353,6006 7352.7,6007 7352.2,6007.8
  region net CMT_FCS: 5649.6,5413.9 5653.8,5418.2 5654.7,5417.4 5655.6,5416.9 5656.5,5416.6 5657.4,5416.5 5659.5,5416.4 5661.8,5416.4 5651.4,5406 5651.4,5408.3 5651.3,5410.3 5651.1,5411.3 5650.8,5412.2 5650.3,5413.1
  region net DI: 5814.2,5394.3 5808.2,5394.3 5808.1,5395.4 5807.8,5396.4 5807.4,5397.2 5806.9,5398 5805.5,5399.5 5803.9,5401.1 5818.5,5401.1 5817,5399.5 5815.6,5398 5815,5397.2 5814.6,5396.4 5814.3,5395.4
  region net SHUNT_RX: 5790.5,5165.1 5794.7,5169.4 5795.6,5168.7 5796.5,5168.2 5797.4,5167.9 5798.3,5167.7 5800.4,5167.6 5802.6,5167.6 5792.3,5157.2 5792.2,5159.5 5792.2,5161.5 5792,5162.5 5791.7,5163.4 5791.2,5164.3
  region net SHUNT_RX: 5603.8,5394.9 5599.6,5399.1 5600.3,5400 5600.8,5400.9 5601.1,5401.8 5601.3,5402.8 5601.4,5404.8 5601.4,5407.1 5611.8,5396.7 5609.5,5396.7 5607.4,5396.6 5606.5,5396.4 5605.6,5396.1 5604.7,5395.6
  region net SHUNT_TX: 5572.8,5399.1 5568.6,5394.9 5567.7,5395.6 5566.8,5396.1 5565.9,5396.4 5565,5396.6 5563,5396.7 5560.7,5396.7 5571,5407.1 5571.1,5404.8 5571.1,5402.8 5571.3,5401.8 5571.6,5400.9 5572.1,5400
  region net MPPT1_RX: 5503.8,5394.9 5499.6,5399.1 5500.3,5400 5500.8,5400.9 5501.1,5401.8 5501.3,5402.8 5501.4,5404.8 5501.4,5407.1 5511.8,5396.7 5509.5,5396.7 5507.4,5396.6 5506.5,5396.4 5505.6,5396.1 5504.7,5395.6
  region net MPPT1_TX: 5464.2,5393.1 5458.2,5393.1 5458.1,5394.2 5457.8,5395.2 5457.4,5396 5456.9,5396.8 5455.5,5398.3 5453.9,5400 5468.5,5400 5467,5398.3 5465.6,5396.8 5465,5396 5464.6,5395.2 5464.3,5394.2
  region net MPPT1_TX: 5439.5,5138.4 5443.7,5134.1 5443,5133.3 5442.5,5132.4 5442.2,5131.5 5442,5130.5 5442,5128.5 5441.9,5126.2 5431.6,5136.6 5433.8,5136.6 5435.9,5136.7 5436.8,5136.9 5437.7,5137.2 5438.6,5137.7
  region net MPPT1_RX: 5474.2,5140.2 5480.2,5140.2 5480.3,5139.1 5480.6,5138.1 5481,5137.2 5481.6,5136.5 5483,5135 5484.6,5133.3 5469.9,5133.3 5471.5,5135 5472.9,5136.5 5473.4,5137.2 5473.8,5138.1 5474.1,5139.1
  region net MPPT2_RX: 5564.2,5353.1 5558.2,5353.1 5558.1,5354.2 5557.8,5355.2 5557.4,5356 5556.9,5356.8 5555.5,5358.3 5553.9,5360 5568.5,5360 5567,5358.3 5565.6,5356.8 5565,5356 5564.6,5355.2 5564.3,5354.2
  region net MPPT2_TX: 5157.5,5707.6 5157.5,5701.6 5156.3,5701.5 5155.4,5701.3 5154.5,5700.8 5153.7,5700.3 5152.2,5698.9 5150.6,5697.3 5150.6,5712 5152.2,5710.4 5153.7,5709 5154.5,5708.4 5155.4,5708 5156.3,5707.7
  region net SHUNT_TX: 5747.7,5154.7 5747.7,5160.7 5748.9,5160.8 5749.9,5161.1 5750.7,5161.5 5751.5,5162.1 5753,5163.5 5754.6,5165.1 5754.6,5150.4 5753,5152 5751.5,5153.4 5750.7,5153.9 5749.9,5154.4 5748.9,5154.7
  region net OLED_SDA: 5349.6,5413.9 5353.8,5418.2 5354.7,5417.4 5355.6,5416.9 5356.5,5416.6 5357.4,5416.5 5359.5,5416.4 5361.8,5416.4 5351.4,5406 5351.4,5408.3 5351.3,5410.3 5351.1,5411.3 5350.8,5412.2 5350.3,5413.1
  region net OLED_SCL: 5025.7,5394.9 5021.5,5399.1 5022.2,5400 5022.7,5400.9 5023,5401.8 5023.2,5402.7 5023.2,5404.8 5023.3,5407.1 5033.6,5396.7 5031.4,5396.7 5029.3,5396.6 5028.4,5396.4 5027.5,5396.1 5026.6,5395.6
  region net OLED_SDA: 5040.5,5378.2 5044.7,5373.9 5044,5373.1 5043.5,5372.2 5043.2,5371.3 5043,5370.3 5043,5368.3 5042.9,5366 5032.6,5376.4 5034.8,5376.4 5036.9,5376.5 5037.8,5376.6 5038.7,5376.9 5039.6,5377.4
  region net DI: 5768.6,5222.3 5772.8,5218 5772.1,5217.2 5771.6,5216.3 5771.3,5215.4 5771.1,5214.4 5771.1,5212.4 5771,5210.1 5760.7,5220.5 5762.9,5220.5 5765,5220.6 5765.9,5220.8 5766.8,5221.1 5767.7,5221.6
  region net OLED_SCL: 5021.5,5333.9 5025.7,5338.2 5026.6,5337.4 5027.5,5336.9 5028.4,5336.6 5029.3,5336.5 5031.4,5336.4 5033.6,5336.4 5023.3,5326 5023.2,5328.3 5023.2,5330.3 5023,5331.3 5022.7,5332.2 5022.2,5333.1
  region net DE: 5297.8,5403.5 5297.8,5409.5 5298.9,5409.6 5299.9,5409.9 5300.7,5410.3 5301.5,5410.9 5303,5412.3 5304.7,5413.9 5304.7,5399.2 5303,5400.8 5301.5,5402.2 5300.7,5402.7 5299.9,5403.2 5298.9,5403.4
  region net DE: 5043.6,5297.5 5045.1,5290.5 5044.3,5289.6 5043.8,5288.8 5043.2,5287.2 5043,5285.5 5042.4,5283.3 5035.2,5296.1 5037.5,5295.8 5039.7,5295.8 5040.8,5296 5041.8,5296.3 5042.8,5296.8
  region net PY_CAN_RX: 4996.1,5393.1 4990.1,5393.1 4990,5394.2 4989.7,5395.2 4989.3,5396 4988.7,5396.8 4987.4,5398.3 4985.8,5400 5000.4,5400 4998.8,5398.3 4997.5,5396.8 4996.9,5396 4996.5,5395.2 4996.2,5394.2
  region net RO: 4979.6,5443.5 4979.6,5449.5 4980.8,5449.6 4981.8,5449.9 4982.6,5450.3 4983.4,5450.9 4984.9,5452.3 4986.5,5453.9 4986.5,5439.2 4984.9,5440.8 4983.4,5442.2 4982.6,5442.7 4981.8,5443.2 4980.8,5443.4
  region net PY_CAN_TX: 4964.7,5399.1 4960.5,5394.9 4959.6,5395.6 4958.7,5396.1 4957.8,5396.4 4956.9,5396.6 4954.8,5396.7 4952.6,5396.7 4962.9,5407.1 4963,5404.8 4963,5402.7 4963.2,5401.8 4963.5,5400.9 4964,5400
  region net RE#: 4956.1,5353.1 4950.1,5353.1 4950,5354.2 4949.7,5355.2 4949.3,5356 4948.7,5356.8 4947.4,5358.3 4945.8,5360 4960.4,5360 4958.8,5358.3 4957.5,5356.8 4956.9,5356 4956.5,5355.2 4956.2,5354.2
  region net RE#: 4950.1,5266.2 4956.1,5266.2 4956.2,5265.1 4956.5,5264.1 4956.9,5263.2 4957.5,5262.5 4958.8,5261 4960.4,5259.3 4945.8,5259.3 4947.4,5261 4948.7,5262.5 4949.3,5263.2 4949.7,5264.1 4950,5265.1
  region net RO: 4920.5,5264.4 4924.7,5260.1 4924,5259.3 4923.5,5258.4 4923.2,5257.5 4923,5256.5 4923,5254.5 4922.9,5252.2 4912.6,5262.6 4914.8,5262.6 4916.9,5262.7 4917.8,5262.9 4918.7,5263.2 4919.6,5263.7
  region net PY_CAN_RX: 4990.1,5266.2 4996.1,5266.2 4996.2,5265.1 4996.5,5264.1 4996.9,5263.2 4997.5,5262.5 4998.8,5261 5000.4,5259.3 4985.8,5259.3 4987.4,5261 4988.7,5262.5 4989.3,5263.2 4989.7,5264.1 4990,5265.1
  region net PY_CAN_TX: 4981.5,5220.1 4985.7,5224.4 4986.6,5223.7 4987.5,5223.2 4988.4,5222.8 4989.3,5222.7 4991.4,5222.6 4993.6,5222.6 4983.3,5212.2 4983.2,5214.5 4983.2,5216.5 4983,5217.5 4982.7,5218.4 4982.2,5219.3
  region net RX3: 5116.8,4714.4 5121.1,4710.1 5120.3,4709.3 5119.8,4708.4 5119.5,4707.5 5119.4,4706.5 5119.3,4704.5 5119.3,4702.2 5108.9,4712.6 5111.2,4712.6 5113.2,4712.7 5114.2,4712.9 5115.1,4713.2 5116,4713.7
  region net TX3: 5162.9,4705.7 5162.9,4699.7 5161.8,4699.7 5160.8,4699.4 5159.9,4698.9 5159.1,4698.4 5157.6,4697 5156,4695.4 5156,4710.1 5157.6,4708.5 5159.1,4707.1 5159.9,4706.5 5160.8,4706.1 5161.8,4705.8
  region net GND: 7446.9,4400.2 7446.9,4415.2 7449.1,4415.3 7451.1,4415.6 7454.7,4416.4 7457.3,4417.2 7458.7,4417.6 7458.7,4397.9 7457.3,4398.3 7454.7,4399.1 7451.1,4399.9 7449.1,4400.1
  region net GND: 7472.4,4404.7 7461.8,4394.1 7460.2,4395.6 7458.6,4396.8 7455.5,4398.7 7453,4400 7451.8,4400.8 7465.7,4414.7 7466.4,4413.4 7467.7,4411 7469.7,4407.9 7470.9,4406.3
  region net GND: 7390.7,4394.1 7380.1,4404.7 7381.5,4406.3 7382.8,4407.9 7384.7,4411 7386,4413.4 7386.8,4414.7 7400.7,4400.8 7399.4,4400 7397,4398.7 7393.9,4396.8 7392.3,4395.6
  region net GND: 7405.5,4415.2 7405.5,4400.2 7403.4,4400.1 7401.3,4399.9 7397.8,4399.1 7395.2,4398.3 7393.7,4397.9 7393.7,4417.6 7395.2,4417.2 7397.8,4416.4 7401.3,4415.6 7403.4,4415.3

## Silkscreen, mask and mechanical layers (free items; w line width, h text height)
Mechanical Layer:
  lines w0.1: 5172.3,6203.7 5172.3,6466.8 5899.1,6466.8 5899.1,6203.7 5172.3,6203.7 ; 6491.1,6240.7 6491.1,6469.7 6981.1,6469.7 6981.1,6240.7 6491.1,6240.7
3D Shell Outline Layer:
  pour cut-out: 4935,3356.3 4935,3120.1 5368.1,3120.1 5368.1,3356.3
  pour cut-out: 5548.2,3356.3 5548.2,3120.1 5981.3,3120.1 5981.3,3356.3
  pour cut-out: 6160.4,3356.3 6160.4,3120.1 6593.5,3120.1 6593.5,3356.3
  pour cut-out: 6682.1,3052.2 7125.1,3052.2 7125.1,3356.3 6682.1,3356.3
  pour cut-out: 4131.8,3478.4 4131.8,3000 4742.1,3000 4742.1,3478.4
  pour cut-out: 7328.3,3372.1 ccw(c7328.3,3293.3) 7249.6,3293.3 7249.6,3272.7 ccw(c7328.3,3272.7) 7328.3,3193.9 7560.6,3193.9 ccw(c7560.6,3272.7) 7639.4,3272.7 7639.4,3293.3 ccw(c7560.6,3293.3) 7560.6,3372.1
  pour cut-out: 3157.5,7400.8 ccw(c3157.5,7243.3) 3000,7243.3 3000,4199.9 ccw(c3157.5,4199.9) 3157.5,4042.4 8551.2,4042.4 ccw(c8551.2,4199.9) 8708.7,4199.9 8708.7,7243.3 ccw(c8551.2,7243.3) 8551.2,7400.8 3157.5,7400.8
3D Shell Top Layer:
  drawing of 26 lines, arcs and shapes, not listed
3D Shell Bottom Layer:
  drawing of 14 lines, arcs and shapes, not listed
